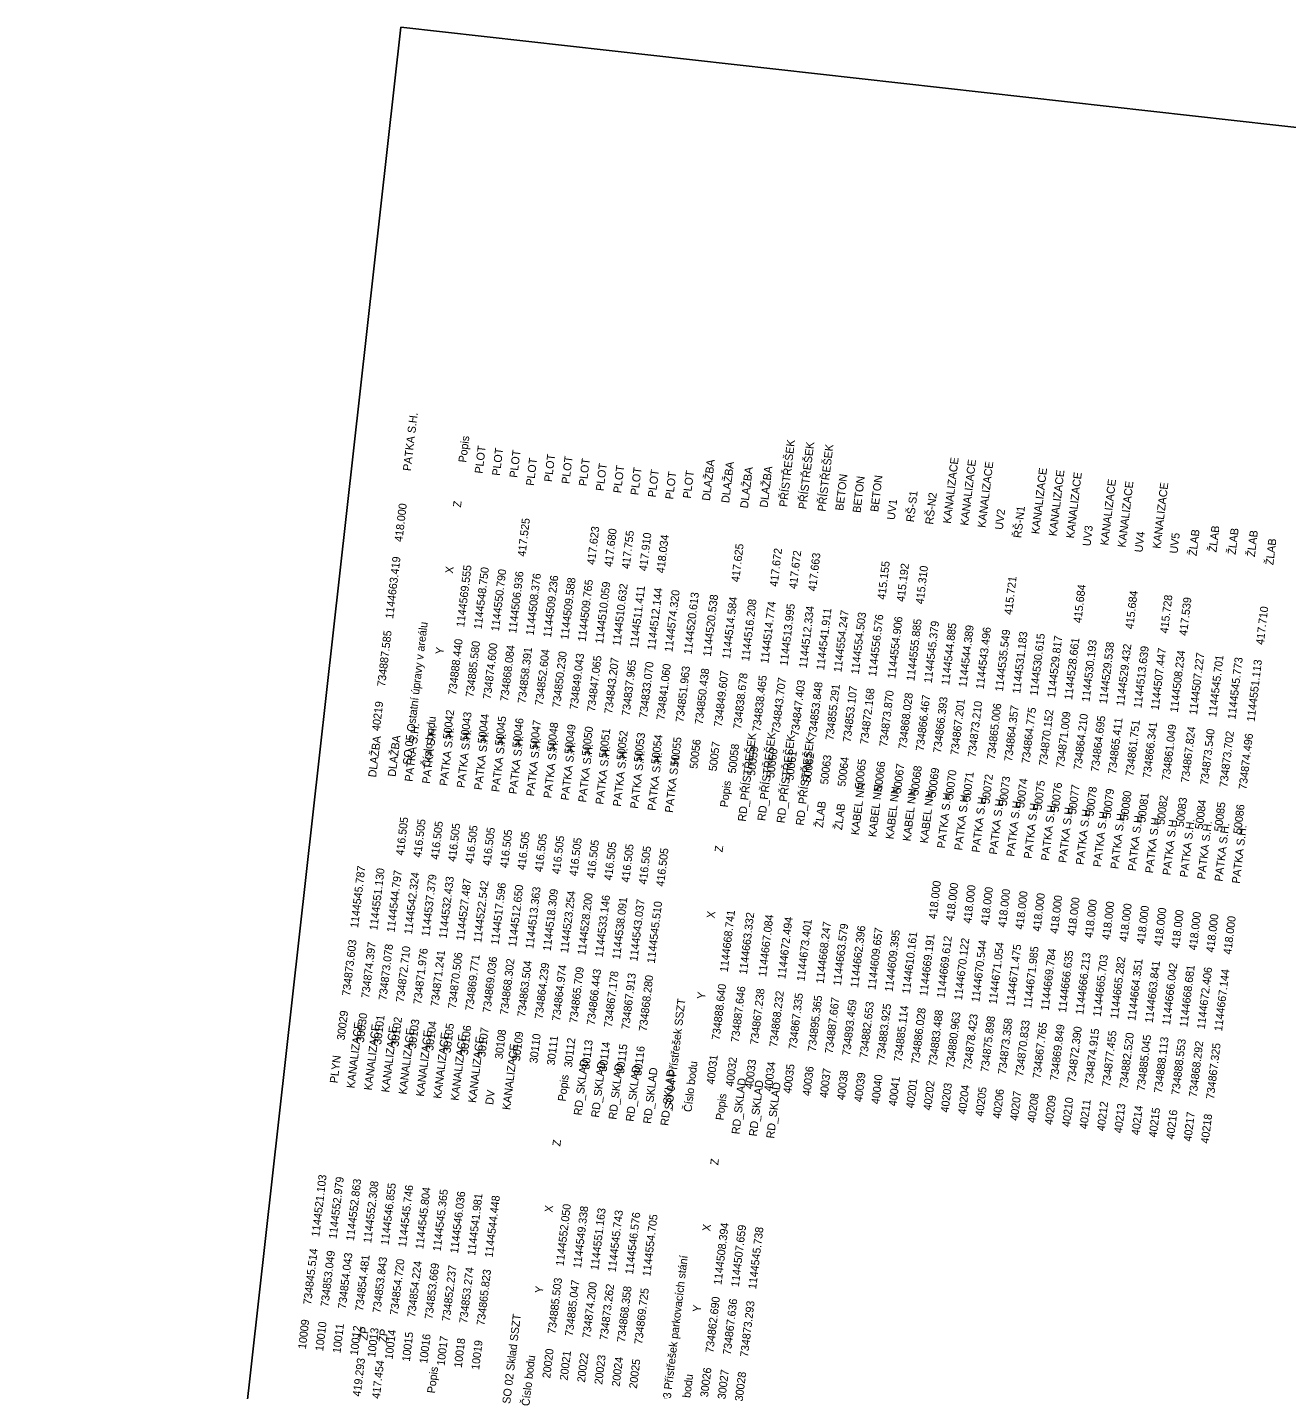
# Model space of a CAD drawing. Extents: x -734953 to -734775, y -1144697 to -1144368.
# Drawn here: x -734953.2 to -734835.1, y -1144495.7 to -1144368 of the extents above; entities that cross this region are included whole.
import ezdxf

# ---------------------------------------------------------------- set-up
doc = ezdxf.new("R2010")
doc.units = 0
doc.layers.add('000_rozpiska', color=7, linetype='Continuous')
doc.layers.add('PROGI_rozpiska', color=7, linetype='Continuous')

msp = doc.modelspace()

# ---------------------------------------------------------------- linework, layer by layer
at = {"layer": '000_rozpiska'}
for p in [(-734953.24, -1144681.04), (-734774.61, -1144384.06)]:
    msp.add_line(p, (-734918.21, -1144367.99), dxfattribs=at)

# ---------------------------------------------------------------- texts
at = {"layer": 'PROGI_rozpiska'}
for s, p in [('          40219     734887.585    1144663.419     418.000           PATKA S.H.', (-734920.52, -1144436.74)), ('Číslo bodu                     Y                         X                    Z             Popis', (-734915.49, -1144437.37)), ('          50042     734888.440    1144569.555                               PLOT', (-734913.86, -1144437.53)), ('          50043     734885.580    1144548.750                               PLOT', (-734912.23, -1144437.73)), ('          50044     734874.600    1144550.790                               PLOT', (-734910.6, -1144437.92)), ('          50059     734838.465    1144514.774     417.672              PŘÍSTŘEŠEK', (-734885.34, -1144440.94)), ('          50060     734843.707    1144513.995     417.672              PŘÍSTŘEŠEK', (-734883.54, -1144441.15)), ('          50061     734847.403    1144512.334     417.663              PŘÍSTŘEŠEK', (-734881.74, -1144441.37)), ('          50045     734868.084    1144506.936     417.525           PLOT', (-734908.98, -1144438.12)), ('          50046     734858.391    1144508.376                               PLOT', (-734907.35, -1144438.31)), ('          50047     734852.604    1144509.236                               PLOT', (-734905.72, -1144438.5)), ('          50048     734850.230    1144509.588                               PLOT', (-734904.1, -1144438.7)), ('          50049     734849.043    1144509.765     417.623            PLOT', (-734902.47, -1144438.89)), ('          50055     734851.963    1144520.613                               DLAŽBA', (-734892.54, -1144440.08)), ('          50056     734850.438    1144520.538                               DLAŽBA', (-734890.74, -1144440.29)), ('          50068     734866.467    1144545.379                                 KANALIZACE', (-734870.02, -1144442.77)), ('          50069     734866.393    1144544.885                                 KANALIZACE', (-734868.39, -1144442.96)), ('          50070     734867.201    1144544.389                                 KANALIZACE', (-734866.77, -1144443.16)), ('          50050     734847.065    1144510.059     417.680            PLOT', (-734900.84, -1144439.09)), ('          50051     734843.207    1144510.632     417.755            PLOT', (-734899.22, -1144439.28)), ('          50052     734837.965    1144511.411     417.910            PLOT', (-734897.59, -1144439.48)), ('          50053     734833.070    1144512.144     418.034            PLOT', (-734895.96, -1144439.67)), ('          50054     734841.060    1144574.320                               PLOT', (-734894.34, -1144439.86)), ('          50057     734849.607    1144514.584     417.625            DLAŽBA', (-734888.94, -1144440.51)), ('          50058     734838.678    1144516.208                               DLAŽBA', (-734887.14, -1144440.72)), ('          50062     734853.848    1144541.911                                 BETON', (-734880.11, -1144441.56)), ('          50063     734855.291    1144554.247                                 BETON', (-734878.49, -1144441.76)), ('          50064     734853.107    1144554.503                                  BETON', (-734876.86, -1144441.95)), ('          50073     734864.357    1144531.183                                 KANALIZACE', (-734861.73, -1144443.76)), ('          50074     734864.775    1144530.615                                 KANALIZACE', (-734860.1, -1144443.95)), ('          50075     734870.152    1144529.817                                 KANALIZACE', (-734858.47, -1144444.15)), ('          50077     734864.210    1144530.193                                KANALIZACE', (-734855.23, -1144444.54)), ('          50078     734864.695    1144529.538                                KANALIZACE', (-734853.6, -1144444.73)), ('          50080     734861.751    1144513.639                                 KANALIZACE', (-734850.36, -1144445.12)), ('          50065     734872.168    1144556.576     415.155              UV1', (-734875.24, -1144442.15)), ('          50066     734873.870    1144554.906     415.192              RŠ-S1', (-734873.44, -1144442.36)), ('          50067     734868.028    1144555.885     415.310              RŠ-N2', (-734871.65, -1144442.58)), ('          50071     734873.210    1144543.496                                 UV2', (-734865.15, -1144443.35)), ('          50072     734865.006    1144535.549     415.721             ŘŠ-N1', (-734863.35, -1144443.57)), ('          50076     734871.009    1144528.661     415.684             UV3', (-734856.86, -1144444.34)), ('          50082     734861.049    1144508.234     417.539              ŽLAB', (-734846.95, -1144445.53)), ('          50083     734867.824    1144507.227                                  ŽLAB', (-734845.15, -1144445.74)), ('          50084     734873.540    1144545.701                                  ŽLAB', (-734843.35, -1144445.96)), ('          50085     734873.702    1144545.773                                  ŽLAB', (-734841.55, -1144446.17)), ('          50079     734865.411    1144529.432     415.684             UV4', (-734851.99, -1144444.92)), ('          50081     734866.341    1144507.447     415.728              UV5', (-734848.74, -1144445.31)), ('          50086     734874.496    1144551.113     417.710              ŽLAB', (-734839.75, -1144446.39)), ('SO 05 Ostatní úpravy v areálu', (-734917.29, -1144437.15)), ('          30030     734874.397    1144551.130                               DLAŽBA', (-734922.01, -1144465.94)), ('          30101     734873.078    1144544.797     416.505            PATKA S.H.', (-734920.39, -1144466.13)), ('          30102     734872.710    1144542.324     416.505            PATKA S.H.', (-734918.76, -1144466.32)), ('          30103     734871.976    1144537.379     416.505            PATKA S.H.', (-734917.13, -1144466.52)), ('          30104     734871.241    1144532.433     416.505            PATKA S.H.', (-734915.51, -1144466.71)), ('          30105     734870.506    1144527.487     416.505            PATKA S.H.', (-734913.88, -1144466.91)), ('          30106     734869.771    1144522.542     416.505            PATKA S.H.', (-734912.26, -1144467.1)), ('          40031     734888.640    1144668.741                              RD_PŘÍSTŘEŠEK', (-734889.15, -1144469.86)), ('          40032     734887.646    1144663.332                               RD_PŘÍSTŘEŠEK', (-734887.35, -1144470.08)), ('          40033     734867.238    1144667.084                               RD_PŘÍSTŘEŠEK', (-734885.55, -1144470.29)), ('          30029     734873.603    1144545.787                              DLAŽBA', (-734923.81, -1144465.72)), ('          30107     734869.036    1144517.596     416.505            PATKA S.H.', (-734910.63, -1144467.3)), ('          30108     734868.302    1144512.650     416.505            PATKA S.H.', (-734909, -1144467.49)), ('          30109     734863.504    1144513.363     416.505            PATKA S.H.', (-734907.38, -1144467.68)), ('          30110     734864.239    1144518.309     416.505            PATKA S.H.', (-734905.75, -1144467.88)), ('          30111     734864.974    1144523.254     416.505            PATKA S.H.', (-734904.12, -1144468.07)), ('          30112     734865.709    1144528.200     416.505            PATKA S.H.', (-734902.5, -1144468.27)), ('          30113     734866.443    1144533.146     416.505            PATKA S.H.', (-734900.87, -1144468.46)), ('          40034     734868.232    1144672.494                               RD_PŘÍSTŘEŠEK', (-734883.75, -1144470.51)), ('          30114     734867.178    1144538.091     416.505            PATKA S.H.', (-734899.25, -1144468.66)), ('          30115     734867.913    1144543.037     416.505            PATKA S.H.', (-734897.62, -1144468.85)), ('          30116     734868.280    1144545.510     416.505            PATKA S.H.', (-734895.99, -1144469.04)), ('Číslo bodu                     Y                         X                    Z             Popis', (-734890.96, -1144469.68)), ('          40037     734887.667    1144663.579                              KABEL NN', (-734878.54, -1144471.13)), ('          40038     734893.459    1144662.396                              KABEL NN', (-734876.92, -1144471.32)), ('          40039     734882.653    1144609.657                              KABEL NN', (-734875.3, -1144471.52)), ('          40040     734883.925    1144609.395                              KABEL NN', (-734873.69, -1144471.71)), ('          40035     734867.335    1144673.401                               ŽLAB', (-734881.95, -1144470.72)), ('          40036     734895.365    1144668.247                               ŽLAB', (-734880.15, -1144470.94)), ('          40041     734885.114    1144610.161                              KABEL NN', (-734872.07, -1144471.9)), ('          40201     734886.028    1144669.191     418.000           PATKA S.H.', (-734870.44, -1144472.1)), ('          40202     734883.488    1144669.612     418.000           PATKA S.H.', (-734868.82, -1144472.29)), ('          40203     734880.963    1144670.122     418.000           PATKA S.H.', (-734867.19, -1144472.49)), ('          40204     734878.423    1144670.544     418.000           PATKA S.H.', (-734865.56, -1144472.68)), ('          40205     734875.898    1144671.054     418.000           PATKA S.H.', (-734863.94, -1144472.87)), ('          40206     734873.358    1144671.475     418.000           PATKA S.H.', (-734862.31, -1144473.07)), ('          40207     734870.833    1144671.985     418.000           PATKA S.H.', (-734860.69, -1144473.26)), ('          40208     734867.765    1144669.784     418.000           PATKA S.H.', (-734859.06, -1144473.46)), ('          40209     734869.849    1144666.635     418.000           PATKA S.H.', (-734857.43, -1144473.65)), ('          40210     734872.390    1144666.213     418.000           PATKA S.H.', (-734855.81, -1144473.85)), ('          40211     734874.915    1144665.703     418.000           PATKA S.H.', (-734854.18, -1144474.04)), ('          40212     734877.455    1144665.282     418.000           PATKA S.H.', (-734852.55, -1144474.23)), ('          40213     734882.520    1144664.351     418.000           PATKA S.H.', (-734850.93, -1144474.43)), ('          40214     734885.045    1144663.841     418.000           PATKA S.H.', (-734849.3, -1144474.62)), ('          40215     734888.113    1144666.042     418.000           PATKA S.H.', (-734847.68, -1144474.82)), ('          40216     734888.553    1144668.681     418.000           PATKA S.H.', (-734846.05, -1144475.01)), ('          40217     734868.292    1144672.406     418.000           PATKA S.H.', (-734844.42, -1144475.21)), ('          40218     734867.325    1144667.144     418.000           PATKA S.H.', (-734842.8, -1144475.4)), ('SO 04 Přístřešek SSZT', (-734892.76, -1144469.46)), ('          10010     734853.049    1144552.979                              KANALIZACE', (-734925.83, -1144494.86)), ('          10011     734854.043    1144552.863                              KANALIZACE', (-734924.2, -1144495.05)), ('          10012     734854.481    1144552.308                              KANALIZACE', (-734922.58, -1144495.25)), ('          10013     734853.843    1144546.855                              KANALIZACE', (-734920.95, -1144495.44)), ('          10014     734854.720    1144545.746                              KANALIZACE', (-734919.32, -1144495.63)), ('          10015     734854.224    1144545.804                              KANALIZACE', (-734917.7, -1144495.83)), ('          10016     734853.669    1144545.365                              KANALIZACE', (-734916.07, -1144496.02)), ('          10017     734852.237    1144546.036                              KANALIZACE', (-734914.44, -1144496.22)), ('          10019     734865.823    1144544.448                             KANALIZACE', (-734911.2, -1144496.61)), ('          10009     734845.514    1144521.103                               PLYN', (-734927.45, -1144494.66)), ('          20020     734885.503    1144552.050                              RD_SKLAD', (-734904.54, -1144497.4)), ('          20021     734885.047    1144549.338                              RD_SKLAD', (-734902.91, -1144497.6)), ('Číslo bodu                     Y                         X                    Z             Popis', (-734906.17, -1144497.24)), ('          20022     734874.200    1144551.163                              RD_SKLAD', (-734901.28, -1144497.79)), ('          20023     734873.262    1144545.743                              RD_SKLAD', (-734899.66, -1144497.98)), ('          20024     734868.358    1144546.576                              RD_SKLAD', (-734898.03, -1144498.18)), ('          20025     734869.725    1144554.705                              RD_SKLAD', (-734896.41, -1144498.37)), ('          10018     734853.274    1144541.981                              DV', (-734912.83, -1144496.41)), ('          30026     734862.690    1144508.394                              RD_SKLAD', (-734889.74, -1144499.17)), ('          30027     734867.636    1144507.659                              RD_SKLAD', (-734888.11, -1144499.36)), ('          30028     734873.293    1144545.738                              RD_SKLAD', (-734886.49, -1144499.56)), ('Číslo bodu                     Y                         X                    Z             Popis', (-734891.37, -1144499.01)), ('SO 03 Přístřešek parkovacích stání', (-734893.17, -1144498.79)), ('SO 02 Sklad SSZT', (-734907.96, -1144497.02)), ('   170100003850                  734870.708           1144648.293     419.293      ŽP', (-734925.33, -1144524.3)), ('   170100003851                 734853.076            1144498.652     417.454      ŽP', (-734923.53, -1144524.51)), ('Číslo bodu                 Y                         X                        Z               Popis', (-734918.49, -1144525.15))]:
    msp.add_text(s, height=0.75, rotation=83.1869, dxfattribs=at).set_placement(p)

doc.saveas('drawing.dxf')
